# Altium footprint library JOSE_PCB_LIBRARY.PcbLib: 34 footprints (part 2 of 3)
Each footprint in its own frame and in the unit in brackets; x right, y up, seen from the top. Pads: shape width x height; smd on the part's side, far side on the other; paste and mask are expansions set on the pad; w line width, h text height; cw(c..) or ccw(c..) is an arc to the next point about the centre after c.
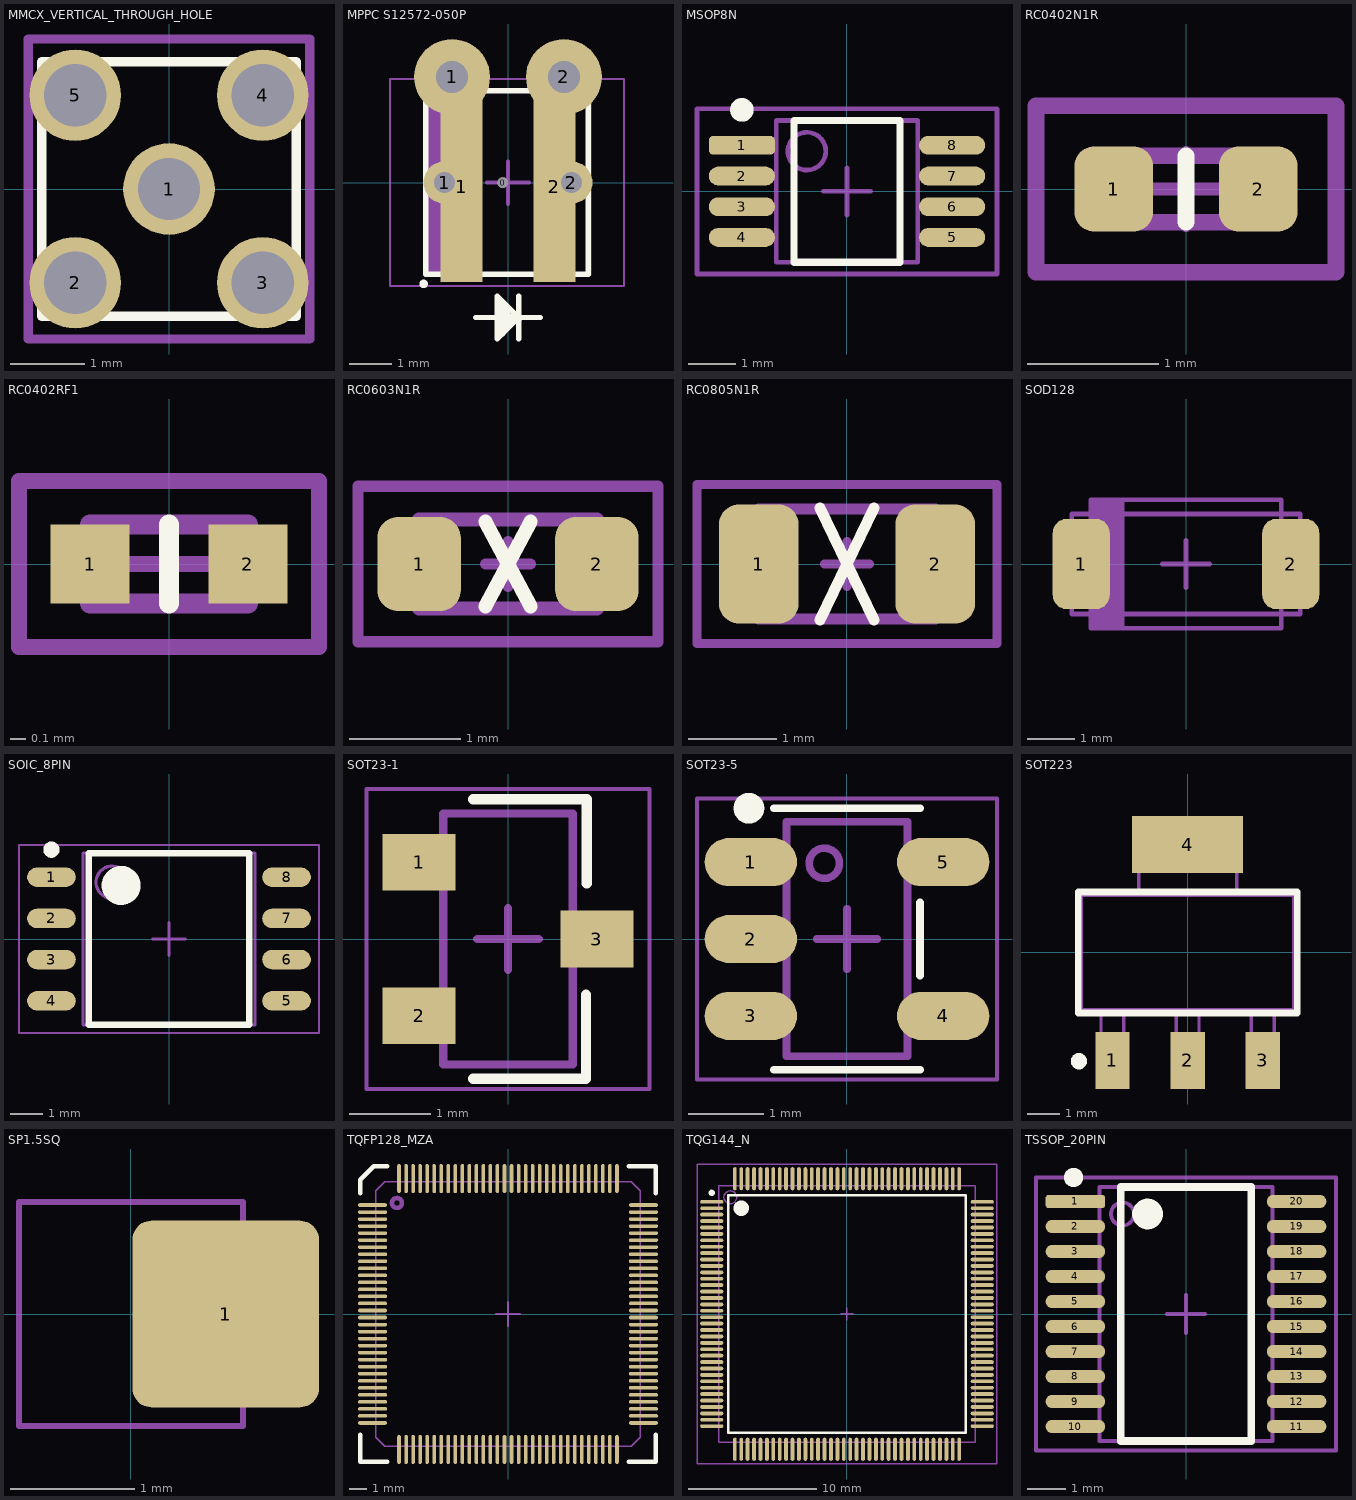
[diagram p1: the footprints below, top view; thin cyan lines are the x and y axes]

## MMCX_VERTICAL_THROUGH_HOLE [mm]
height 7.44
pads (5):
  round 1.24 hole 0.84: 1(0,0) 2(-1.27,-1.27) 3(1.27,-1.27) 4(1.27,1.27) 5(-1.27,1.27)
Top Overlay:
  lines w0.127: -1.725,-1.725 -1.725,1.725 1.725,1.725 1.725,-1.725 -1.725,-1.725
Mechanical 15:
  lines w0.127: -1.905,-2.032 1.905,-2.032 1.905,2.032 -1.905,2.032 -1.905,-2.032
3D body: height 4.42, standoff 0.89, extent -1.26,-1.267 1.27,1.268
3D body: height 0.89, standoff 0, extent -1.727,-1.727 1.727,1.727
3D body: height 3.02, standoff 0, extent -1.518,1.02 -1.018,1.52
3D body: height 3.02, standoff 0, extent 1.02,1.02 1.52,1.52
3D body: height 3.02, standoff 0, extent 1.02,-1.519 1.52,-1.019
3D body: height 3.02, standoff 0, extent -1.518,-1.519 -1.018,-1.019
3D body: height 3.02, standoff 0, extent -0.347,-0.349 0.35,0.349

## MPPC S12572-050P [mm] "MPPC S12572-050P, 2-Leads, Body 3x3mm, IPC Medium Density"
height 1.45
pads (7):
  round 0.25 hole 0.25 unplated paste+0 mask+0: 0(-0.125,0)
  round 1 hole 0.5: 1(-1.5,0) 2(1.5,0)
  round 1.8 hole 0.75: 1(-1.325,2.5) 2(1.325,2.5)
  rect 1x4.5 smd: 1(-1.1,-0.1) 2(1.1,-0.1)
Top Overlay:
  circle w0.1: c-2,-2.4 r0.05
  lines w0.127: -0.762,-3.198 -0.254,-3.198 ; -0.127,-2.817 -0.127,-3.579 0,-3.452 0,-2.944 ; 0.254,-3.706 0.254,-2.69 ; 0.762,-3.198 0.254,-3.198 ; 0.254,-3.198 -0.254,-3.706 -0.254,-2.69 0.254,-3.198 ; -1.95,-2.175 1.9,-2.175 1.9,2.175 -1.95,2.175 -1.95,-2.175
  lines w0.2: -0.127,-3.198 0.254,-3.198
Mechanical 13:
  rectangle: -1.925,-2.175 -1.407,2.175
  lines w0.1: -1.925,-2.175 -1.925,2.175 1.925,2.175 1.925,-2.175 -1.925,-2.175
Mechanical 15:
  lines w0.05: -2.794,-2.45 -2.794,2.45 2.75,2.45 2.75,-2.45 -2.794,-2.45
  lines w0.1: -0.5,0 0.5,0 ; 0,-0.5 0,0.5
3D body: height 1.45, standoff 0, extent -1.925,-2.175 1.925,-1.3
3D body: height 1.45, standoff 0, extent -1.925,-1.3 1.925,2.175

## MSOP8N [mm]
height 1.1
pads (8):
  rrect50% 1.4x0.4 smd mask+0.051: 1(-2.225,0.975)
  oval 1.4x0.4 smd mask+0.051: 2(-2.225,0.325) 3(-2.225,-0.325) 4(-2.225,-0.975) 5(2.225,-0.975) 6(2.225,-0.325) 7(2.225,0.325) 8(2.225,0.975)
Top Overlay:
  circle w0.25: c-2.225,1.725 r0.125
  lines w0.15: -1.125,-1.5 -1.125,1.5 1.125,1.5 1.125,-1.5 -1.125,-1.5
Mechanical 13:
  circle w0.1: c-0.85,0.85 r0.4
  lines w0.1: -1.5,-1.5 -1.5,1.5 1.5,1.5 1.5,-1.5 -1.5,-1.5
Mechanical 15:
  lines w0.1: -0.5,0 0.5,0 ; 0,-0.5 0,0.5 ; -3.175,-1.75 -3.175,1.75 3.175,1.75 3.175,-1.75 -3.175,-1.75
3D body: height 1.11, standoff 1.1, extent -1.248,0.452 -0.452,1.25
3D body: height 1.1, standoff 0.15, extent -1.5,-1.5 1.5,1.5

## RC0402N1R [mm] "Chip capacitor 0402 ROUNDED PAD"
height 0.5
pads (2):
  rrect50% 0.6x0.65 smd: 1(-0.55,0) 2(0.55,0)
Top Overlay:
  lines w0.127: 0,-0.254 0,0.254
Mechanical 13:
  lines w0.127: -0.508,-0.254 0.508,-0.254 0.508,0.254 -0.508,0.254 -0.508,-0.254
Mechanical 15:
  lines w0.102: -0.3,0 0.3,0 ; 0,-0.275 0,0.275
  lines w0.127: -1.143,-0.635 -1.143,0.635 1.143,0.635 1.143,-0.635 -1.143,-0.635
3D body: height 0.36, standoff 0.35, extent -0.35,-0.254 0.35,0.254
3D body: height 0.35, standoff 0, extent -0.508,-0.254 0.508,0.254

## RC0402RF1 [mil] "Chip resistor 0402 RF pad"
height 15.75
pads (2):
  rect 20x20 smd: 1(-20,0) 2(20,0)
Top Overlay:
  lines w5: 0,-10 0,10
Mechanical 13:
  lines w5: -20,-10 20,-10 20,10 -20,10 -20,-10
Mechanical 15:
  lines w3.94: -9.84,0 9.84,0 ; 0,-9.84 0,9.84
  lines w4: -38,-21 -38,21 38,21 38,-21 -38,-21
3D body: height 13.78, standoff 0, extent -20,-10 20,10
3D body: height 13.98, standoff 13.78, extent -13.78,-10 13.78,10

## RC0603N1R [mm] "Chip resistor 0603 ROUNDED PAD"
height 0.45
pads (2):
  rrect50% 0.75x0.85 smd: 1(-0.8,0) 2(0.8,0)
Top Overlay:
  lines w0.127: -0.203,-0.381 0.203,0.381 ; -0.203,0.381 0.203,-0.381
Mechanical 13:
  lines w0.127: -0.8,-0.4 0.8,-0.4 0.8,0.4 -0.8,0.4 -0.8,-0.4
Mechanical 15:
  lines w0.1: -0.2,0 0.2,0 ; 0,-0.2 0,0.2 ; -1.35,-0.7 1.35,-0.7 1.35,0.7 -1.35,0.7 -1.35,-0.7
3D body: height 0.46, standoff 0.45, extent -0.6,-0.4 0.6,0.4
3D body: height 0.45, standoff 0, extent -0.8,-0.4 0.8,0.4

## RC0805N1R [mm] "Chip resistor 0805 ROUNDED PAD"
height 0.5
pads (2):
  rrect50% 0.9x1.35 smd: 1(-1,0) 2(1,0)
Top Overlay:
  lines w0.127: -0.305,-0.635 0.305,0.635 ; -0.305,0.635 0.305,-0.635
Mechanical 13:
  lines w0.127: -1,-0.625 1,-0.625 1,0.625 -1,0.625 -1,-0.625
Mechanical 15:
  lines w0.1: -0.254,0 0.254,0 ; 0,-0.254 0,0.254 ; -1.7,-0.9 1.7,-0.9 1.7,0.9 -1.7,0.9 -1.7,-0.9
3D body: height 0.51, standoff 0.5, extent -0.6,-0.625 0.6,0.625
3D body: height 0.5, standoff 0, extent -1.016,-0.625 1.016,0.625

## SOD128 [mm] "2-Leads, Body 2.7x4.0mm (max), IPC Medium Density"
height 1.1
pads (2):
  rrect50% 1.2x1.9 smd: 1(-2.2,0) 2(2.2,0)
Mechanical 13:
  region: -2,-1.35 -2,1.35 -1.3,1.35 -1.3,-1.35
  lines w0.1: -2,-1.35 2,-1.35 2,1.35 -2,1.35 -2,-1.35
Mechanical 15:
  lines w0.1: -0.5,0 0.5,0 ; 0,-0.5 0,0.5 ; -2.4,-1.05 2.4,-1.05 2.4,1.05 -2.4,1.05 -2.4,-1.05
3D body: height 1.1, standoff 0, extent -2,-1.35 -1.3,1.35
3D body: height 1.1, standoff 0, extent -1.3,-1.35 2,1.35

## SOIC_8PIN [mm] "SOIC, 8-Leads, Body 5.28x5.28mm, Pitch 1.27mm, IPC Medium Density"
height 1.95
pads (8):
  oval 1.5x0.6 smd: 1(-3.625,1.905) 2(-3.625,0.635) 3(-3.625,-0.635) 4(-3.625,-1.905) 5(3.625,-1.905) 6(3.625,-0.635) 7(3.625,0.635) 8(3.625,1.905)
Top Overlay:
  circle w0.6: c-1.475,1.65 r0.3
  circle w0.25: c-3.625,2.755 r0.125
  lines w0.2: -2.475,-2.65 2.475,-2.65 2.475,2.65 -2.475,2.65 -2.475,-2.65
Mechanical 13:
  circle w0.1: c-1.75,1.75 r0.5
  lines w0.1: -2.65,-2.65 2.65,-2.65 2.65,2.65 -2.65,2.65 -2.65,-2.65
Mechanical 15:
  lines w0.05: -4.625,-2.9 4.625,-2.9 4.625,2.9 -4.625,2.9 -4.625,-2.9
  lines w0.1: -0.5,0 0.5,0 ; 0,-0.5 0,0.5
3D body: height 1.95, standoff 0.15, extent -2.65,-2.65 2.65,2.65

## SOT23-1 [mm]
height 1.016
pads (3):
  rect 0.9x0.7 smd: 1(-1.1,0.95) 2(-1.1,-0.95) 3(1.1,0)
Top Overlay:
  lines w0.127: -0.432,-1.727 0.965,-1.727 0.965,-0.689 ; -0.432,1.727 0.975,1.727 0.975,0.686
Mechanical 13:
  lines w0.102: -0.8,-1.55 -0.8,1.55 0.8,1.55 0.8,-1.55 -0.8,-1.55
Mechanical 15:
  lines w0.051: -1.75,-1.854 -1.75,1.854 1.75,1.854 1.75,-1.854 -1.75,-1.854
  lines w0.102: -0.381,0 0.381,0 ; 0,-0.381 0,0.381
3D body: height 0.3, standoff 0, extent 0.8,-0.225 1.275,0.225
3D body: height 0.3, standoff 0, extent -1.275,-1.175 -0.8,-0.725
3D body: height 0.3, standoff 0, extent -1.275,0.725 -0.8,1.175
3D body: height 1.02, standoff 0, extent -0.8,-1.55 0.8,1.55

## SOT23-5 [mil]
height 40
pads (5):
  oval 48x25 smd mask+2: 1(-50,40) 2(-50,0) 3(-50,-40) 4(50,-40) 5(50,40)
Top Overlay:
  circle w8: c-51,68 r4
  lines w4: -38,-68 38,-68 ; -38,68 38,68 ; 38,-19 38,19
Mechanical 13:
  circle w3.94: c-11.81,39.37 r7.87
  lines w4: -31.5,-61.02 31.5,-61.02 31.5,61.02 -31.5,61.02 -31.5,-61.02
Mechanical 15:
  lines w2: -78,-73 78,-73 78,73 -78,73 -78,-73
  lines w4: -15.75,0 15.75,0 ; 0,-15.75 0,15.75
3D body: height 11.81, standoff 0, extent 31.5,-48.23 50.2,-30.51
3D body: height 11.81, standoff 0, extent 31.5,30.51 50.2,48.23
3D body: height 11.81, standoff 0, extent -50.2,-8.86 -31.5,8.86
3D body: height 11.81, standoff 0, extent -50.2,-48.23 -31.5,-30.51
3D body: height 11.81, standoff 0, extent -50.2,30.51 -31.5,48.23
3D body: height 57.09, standoff 0, extent -31.5,-61.02 31.5,61.02
3D body: height 57.48, standoff 57.09, extent -19.69,31.5 -3.94,47.24

## SOT223 [mm]
height 1.8
pads (4):
  rect 1.05x1.75 smd: 1(-2.3,-3.3) 2(0,-3.3) 3(2.3,-3.3)
  rect 3.4x1.75 smd: 4(0,3.3)
Top Overlay:
  circle w0.25: c-3.325,-3.325 r0.125
  lines w0.203: -3.35,-1.85 3.35,-1.85 3.35,1.85 -3.35,1.85 -3.35,-1.85
Mechanical 13:
  lines w0.102: -2.65,-1.75 -2.65,-3.5 -1.95,-3.5 -1.95,-1.75 ; -1.5,1.75 -1.5,3.5 1.5,3.5 1.5,1.75 ; -0.35,-1.75 -0.35,-3.5 0.35,-3.5 0.35,-1.75 ; 1.95,-1.75 1.95,-3.5 2.65,-3.5 2.65,-1.75 ; -3.25,-1.75 -3.25,1.75 3.25,1.75 3.25,-1.75 -3.25,-1.75
3D body: height 1.8, standoff 0, extent -3.25,-1.75 3.25,1.75
3D body: height 1, standoff 0.8, extent -2.65,-2.75 -1.95,-1.75
3D body: height 1, standoff 0, extent -2.65,-2.75 -1.95,-2.55
3D body: height 0.2, standoff 0, extent -2.65,-3.5 -1.95,-2.75
3D body: height 0.2, standoff 0, extent -0.35,-3.5 0.35,-2.75
3D body: height 1, standoff 0, extent -0.35,-2.75 0.35,-2.55
3D body: height 1, standoff 0.8, extent -0.35,-2.75 0.35,-1.75
3D body: height 0.2, standoff 0, extent 1.95,-3.5 2.65,-2.75
3D body: height 1, standoff 0, extent 1.95,-2.75 2.65,-2.55
3D body: height 1, standoff 0.8, extent 1.95,-2.75 2.65,-1.75
3D body: height 0.2, standoff 0, extent -1.5,2.75 1.5,3.5
3D body: height 1, standoff 0, extent -1.5,2.55 1.5,2.75
3D body: height 1, standoff 0.8, extent -1.5,1.75 1.5,2.75

## SP1.5SQ [mm] "Solder Pad 1.5mm SMT"
height 0.5
pads (1):
  rrect20% 1.5x1.5 smd: 1(0.762,0)
Mechanical 13:
  lines w0.05: -0.9,-0.9 -0.9,0.9 0.9,0.9 0.9,-0.9 -0.9,-0.9

## TQFP128_MZA [mil]
height 47.24
pads (128):
  oval 65x8 smd mask+2: 1(-302.5,243.35) 2(-302.5,227.65) 3(-302.5,211.95) 4(-302.5,196.25) 5(-302.5,180.55) 6(-302.5,164.85) 7(-302.5,149.15) 8(-302.5,133.45) 9(-302.5,117.75) 10(-302.5,102.05) 11(-302.5,86.35) 12(-302.5,70.65) 13(-302.5,54.95) 14(-302.5,39.25) 15(-302.5,23.55) 16(-302.5,7.85) 17(-302.5,-7.85) 18(-302.5,-23.55) 19(-302.5,-39.25) 20(-302.5,-54.95) 21(-302.5,-70.65) 22(-302.5,-86.35) 23(-302.5,-102.05) 24(-302.5,-117.75) 25(-302.5,-133.45) 26(-302.5,-149.15) 27(-302.5,-164.85) 28(-302.5,-180.55) 29(-302.5,-196.25) 30(-302.5,-211.95) 31(-302.5,-227.65) 32(-302.5,-243.35) 65(302.5,-243.35) 66(302.5,-227.65) 67(302.5,-211.95) 68(302.5,-196.25) 69(302.5,-180.55) 70(302.5,-164.85) 71(302.5,-149.15) 72(302.5,-133.45) 73(302.5,-117.75) 74(302.5,-102.05) 75(302.5,-86.35) 76(302.5,-70.65) 77(302.5,-54.95) 78(302.5,-39.25) 79(302.5,-23.55) 80(302.5,-7.85) 81(302.5,7.85) 82(302.5,23.55) 83(302.5,39.25) 84(302.5,54.95) 85(302.5,70.65) 86(302.5,86.35) 87(302.5,102.05) 88(302.5,117.75) 89(302.5,133.45) 90(302.5,149.15) 91(302.5,164.85) 92(302.5,180.55) 93(302.5,196.25) 94(302.5,211.95) 95(302.5,227.65) 96(302.5,243.35)
  oval 8x65 smd mask+2: 33(-243.35,-302.5) 34(-227.65,-302.5) 35(-211.95,-302.5) 36(-196.25,-302.5) 37(-180.55,-302.5) 38(-164.85,-302.5) 39(-149.15,-302.5) 40(-133.45,-302.5) 41(-117.75,-302.5) 42(-102.05,-302.5) 43(-86.35,-302.5) 44(-70.65,-302.5) 45(-54.95,-302.5) 46(-39.25,-302.5) 47(-23.55,-302.5) 48(-7.85,-302.5) 49(7.85,-302.5) 50(23.55,-302.5) 51(39.25,-302.5) 52(54.95,-302.5) 53(70.65,-302.5) 54(86.35,-302.5) 55(102.05,-302.5) 56(117.75,-302.5) 57(133.45,-302.5) 58(149.15,-302.5) 59(164.85,-302.5) 60(180.55,-302.5) 61(196.25,-302.5) 62(211.95,-302.5) 63(227.65,-302.5) 64(243.35,-302.5) 97(243.35,302.5) 98(227.65,302.5) 99(211.95,302.5) 100(196.25,302.5) 101(180.55,302.5) 102(164.85,302.5) 103(149.15,302.5) 104(133.45,302.5) 105(117.75,302.5) 106(102.05,302.5) 107(86.35,302.5) 108(70.65,302.5) 109(54.95,302.5) 110(39.25,302.5) 111(23.55,302.5) 112(7.85,302.5) 113(-7.85,302.5) 114(-23.55,302.5) 115(-39.25,302.5) 116(-54.95,302.5) 117(-70.65,302.5) 118(-86.35,302.5) 119(-102.05,302.5) 120(-117.75,302.5) 121(-133.45,302.5) 122(-149.15,302.5) 123(-164.85,302.5) 124(-180.55,302.5) 125(-196.25,302.5) 126(-211.95,302.5) 127(-227.65,302.5) 128(-243.35,302.5)
Top Overlay:
  lines w10: -330,-270 -330,-330 -270,-330 ; -330,270 -330,300 -300,330 -270,330 ; 270,-330 330,-330 330,-270 ; 270,330 330,330 330,270
Mechanical 13:
  circle w10: c-248.03,248.03 r11.14
  lines w3.94: -295.28,-275.59 -275.59,-295.28 275.59,-295.28 295.28,-275.59 295.28,275.59 275.59,295.28 -275.59,295.28 -295.28,275.59 -295.28,-275.59
Mechanical 15:
  lines w3.94: -27.56,0 27.56,0 ; 0,-27.56 0,27.56
3D body: height 47.24, standoff 0, extent -295.28,-295.28 295.28,295.28
3D body: height 47.64, standoff 47.24, extent -255.81,220.5 -216.59,259.79

## TQG144_N [mm] "Thin QFP, 144-Leads, Body 20x20mm, Pitch 0.5mm, IPC Medium Density"
height 1.6
pads (144):
  oval 1.8x0.3 smd: 1(-10.55,8.75) 2(-10.55,8.25) 3(-10.55,7.75) 4(-10.55,7.25) 5(-10.55,6.75) 6(-10.55,6.25) 7(-10.55,5.75) 8(-10.55,5.25) 9(-10.55,4.75) 10(-10.55,4.25) 11(-10.55,3.75) 12(-10.55,3.25) 13(-10.55,2.75) 14(-10.55,2.25) 15(-10.55,1.75) 16(-10.55,1.25) 17(-10.55,0.75) 18(-10.55,0.25) 19(-10.55,-0.25) 20(-10.55,-0.75) 21(-10.55,-1.25) 22(-10.55,-1.75) 23(-10.55,-2.25) 24(-10.55,-2.75) 25(-10.55,-3.25) 26(-10.55,-3.75) 27(-10.55,-4.25) 28(-10.55,-4.75) 29(-10.55,-5.25) 30(-10.55,-5.75) 31(-10.55,-6.25) 32(-10.55,-6.75) 33(-10.55,-7.25) 34(-10.55,-7.75) 35(-10.55,-8.25) 36(-10.55,-8.75) 73(10.55,-8.75) 74(10.55,-8.25) 75(10.55,-7.75) 76(10.55,-7.25) 77(10.55,-6.75) 78(10.55,-6.25) 79(10.55,-5.75) 80(10.55,-5.25) 81(10.55,-4.75) 82(10.55,-4.25) 83(10.55,-3.75) 84(10.55,-3.25) 85(10.55,-2.75) 86(10.55,-2.25) 87(10.55,-1.75) 88(10.55,-1.25) 89(10.55,-0.75) 90(10.55,-0.25) 91(10.55,0.25) 92(10.55,0.75) 93(10.55,1.25) 94(10.55,1.75) 95(10.55,2.25) 96(10.55,2.75) 97(10.55,3.25) 98(10.55,3.75) 99(10.55,4.25) 100(10.55,4.75) 101(10.55,5.25) 102(10.55,5.75) 103(10.55,6.25) 104(10.55,6.75) 105(10.55,7.25) 106(10.55,7.75) 107(10.55,8.25) 108(10.55,8.75)
  oval 0.3x1.8 smd: 37(-8.75,-10.55) 38(-8.25,-10.55) 39(-7.75,-10.55) 40(-7.25,-10.55) 41(-6.75,-10.55) 42(-6.25,-10.55) 43(-5.75,-10.55) 44(-5.25,-10.55) 45(-4.75,-10.55) 46(-4.25,-10.55) 47(-3.75,-10.55) 48(-3.25,-10.55) 49(-2.75,-10.55) 50(-2.25,-10.55) 51(-1.75,-10.55) 52(-1.25,-10.55) 53(-0.75,-10.55) 54(-0.25,-10.55) 55(0.25,-10.55) 56(0.75,-10.55) 57(1.25,-10.55) 58(1.75,-10.55) 59(2.25,-10.55) 60(2.75,-10.55) 61(3.25,-10.55) 62(3.75,-10.55) 63(4.25,-10.55) 64(4.75,-10.55) 65(5.25,-10.55) 66(5.75,-10.55) 67(6.25,-10.55) 68(6.75,-10.55) 69(7.25,-10.55) 70(7.75,-10.55) 71(8.25,-10.55) 72(8.75,-10.55) 109(8.75,10.55) 110(8.25,10.55) 111(7.75,10.55) 112(7.25,10.55) 113(6.75,10.55) 114(6.25,10.55) 115(5.75,10.55) 116(5.25,10.55) 117(4.75,10.55) 118(4.25,10.55) 119(3.75,10.55) 120(3.25,10.55) 121(2.75,10.55) 122(2.25,10.55) 123(1.75,10.55) 124(1.25,10.55) 125(0.75,10.55) 126(0.25,10.55) 127(-0.25,10.55) 128(-0.75,10.55) 129(-1.25,10.55) 130(-1.75,10.55) 131(-2.25,10.55) 132(-2.75,10.55) 133(-3.25,10.55) 134(-3.75,10.55) 135(-4.25,10.55) 136(-4.75,10.55) 137(-5.25,10.55) 138(-5.75,10.55) 139(-6.25,10.55) 140(-6.75,10.55) 141(-7.25,10.55) 142(-7.75,10.55) 143(-8.25,10.55) 144(-8.75,10.55)
Top Overlay:
  circle w0.25: c-10.55,9.45 r0.125
  circle w0.6: c-8.25,8.25 r0.3
  lines w0.2: -9.25,-9.25 -9.25,9.25 9.25,9.25 9.25,-9.25 -9.25,-9.25
Mechanical 13:
  circle w0.1: c-9.1,9.1 r0.5
  lines w0.1: -10,-10 -10,10 10,10 10,-10 -10,-10
Mechanical 15:
  lines w0.1: -0.5,0 0.5,0 ; 0,-0.5 0,0.5 ; -11.7,-11.7 -11.7,11.7 11.7,11.7 11.7,-11.7 -11.7,-11.7
3D body: height 1.6, standoff 0, extent -10,-10 10,10

## TSSOP_20PIN [mm] "TSSOP 20, Body 6,6x4,5mm, R0,65mm, IPC Medium Density"
height 1.2
pads (20):
  rrect50% 1.55x0.35 smd mask+0.051: 1(-2.875,2.925)
  oval 1.55x0.35 smd mask+0.051: 2(-2.875,2.275) 3(-2.875,1.625) 4(-2.875,0.975) 5(-2.875,0.325) 6(-2.875,-0.325) 7(-2.875,-0.975) 8(-2.875,-1.625) 9(-2.875,-2.275) 10(-2.875,-2.925) 11(2.875,-2.925) 12(2.875,-2.275) 13(2.875,-1.625) 14(2.875,-0.975) 15(2.875,-0.325) 16(2.875,0.325) 17(2.875,0.975) 18(2.875,1.625) 19(2.875,2.275) 20(2.875,2.925)
Top Overlay:
  circle w0.4: c-1,2.6 r0.2
  circle w0.25: c-2.925,3.55 r0.125
  lines w0.2: -1.7,-3.3 1.7,-3.3 1.7,3.3 -1.7,3.3 -1.7,-3.3
Mechanical 13:
  circle w0.1: c-1.65,2.6 r0.3
  lines w0.1: -2.25,-3.3 2.25,-3.3 2.25,3.3 -2.25,3.3 -2.25,-3.3
Mechanical 15:
  lines w0.1: -0.5,0 0.5,0 ; 0,-0.5 0,0.5 ; -3.9,-3.55 3.9,-3.55 3.9,3.55 -3.9,3.55 -3.9,-3.55
3D body: height 1.2, standoff 0.05, extent -2.25,-3.3 2.25,3.3
3D body: height 1.21, standoff 1.2, extent -1.973,2.301 -1.375,2.899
